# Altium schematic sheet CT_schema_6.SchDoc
size 371 x 245 mm
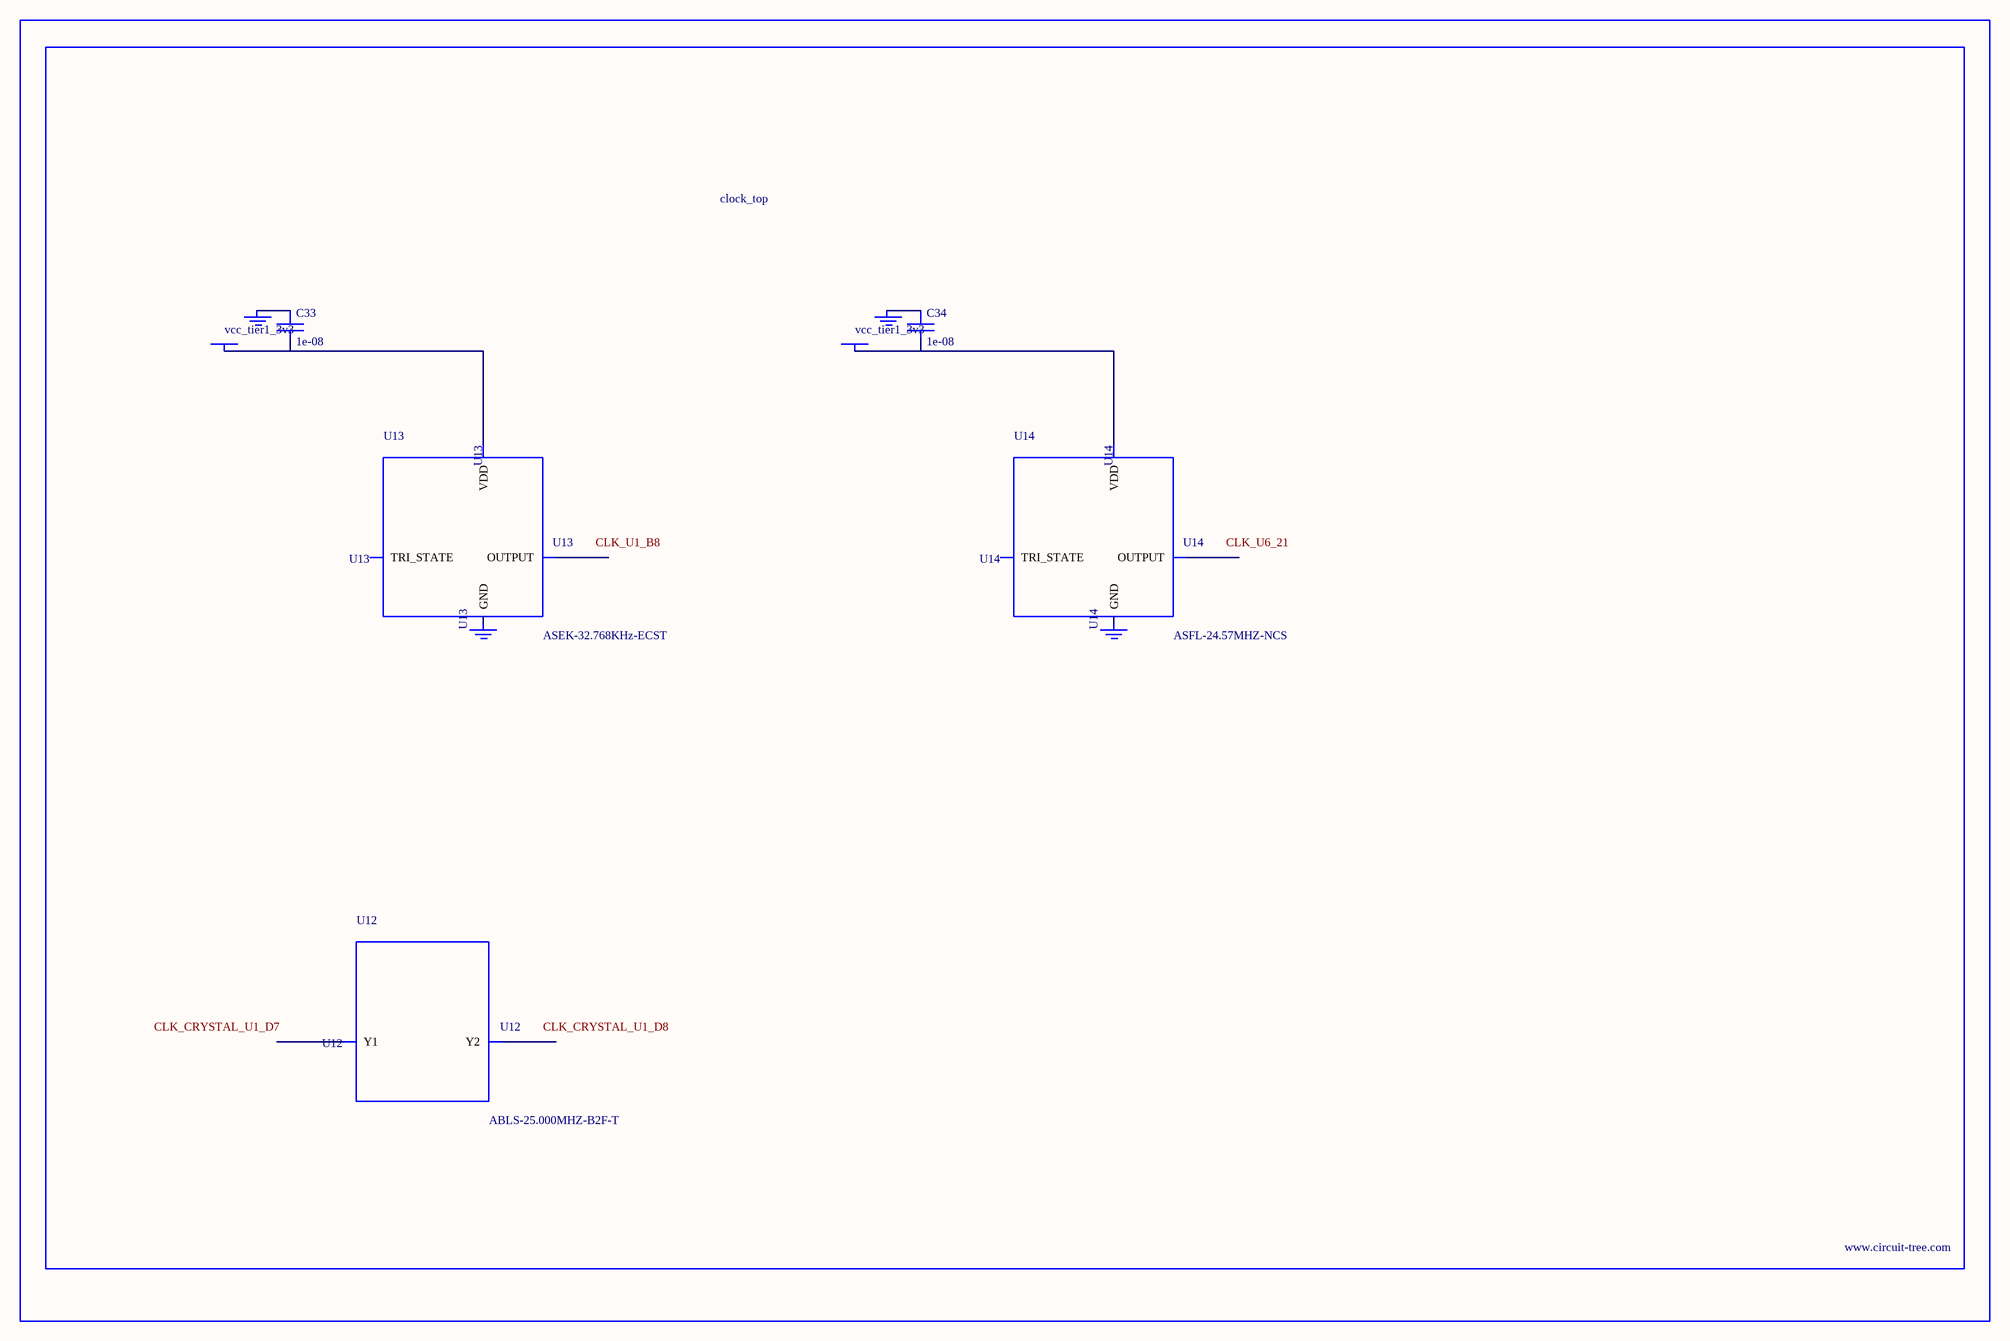
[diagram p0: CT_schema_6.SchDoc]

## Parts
BORDER5  (no value)
C33  1e-08  [C0402]
C34  1e-08  [C0402]
GND_INSTANCE_5_0  (no value)
GND_INSTANCE_5_1  (no value)
GND_INSTANCE_5_2  (no value)
GND_INSTANCE_5_3  (no value)
POWER_INSTANCE_5_0  vcc_tier1_3v3
POWER_INSTANCE_5_1  vcc_tier1_3v3
U12  ABLS-25.000MHZ-B2F-T  [ABLS-25.000MHZ-B2F-T]
U13  ASEK-32.768KHz-ECST  [ASEK]
U14  ASFL-24.57MHZ-NCS  [ASFL1]

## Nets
NetC33_1: C33.1 GND_INSTANCE_5_0.0(GND)
NetC33_2: C33.2 POWER_INSTANCE_5_0.0(PWR) U13.4(VDD)
NetC34_1: C34.1 GND_INSTANCE_5_2.0(GND)
NetC34_2: C34.2 POWER_INSTANCE_5_1.0(PWR) U14.4(VDD)

Not connected (* = marked no-connect by the designer): GND_INSTANCE_5_1 0(GND); GND_INSTANCE_5_3 0(GND); U12 1(Y1) 2(Y2); U13 1(TRI_STATE) 2(GND) 3(OUTPUT); U14 1(TRI_STATE) 2(GND) 3(OUTPUT)

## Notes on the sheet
- Labels drawn without touching a wire or pin: CLK_CRYSTAL_U1_D7, CLK_CRYSTAL_U1_D8, CLK_U1_B8, CLK_U6_21

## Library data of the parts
BORDER5 = BORDER_PAGE5
C33 C34 = C0402C103K3RAC
GND_INSTANCE_5_0-GND_INSTANCE_5_3 = GND
POWER_INSTANCE_5_0 POWER_INSTANCE_5_1 = PWR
